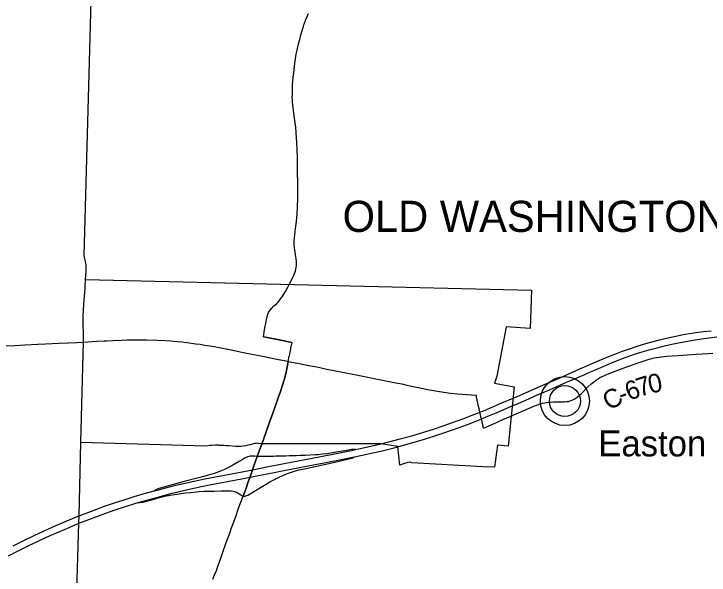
# Model space of a CAD drawing. Extents: x -29.6 to 34, y 0 to 22.
# Drawn here: x -18.092 to -16.109, y 3.352 to 4.953 of the extents above; entities that cross this region are included whole.
import ezdxf

# ---------------------------------------------------------------- set-up
doc = ezdxf.new("R2010")
doc.units = 0
for name, color, linetype in [('GM_X_City_Street', 7, 'Continuous'), ('GM_X_Corporation', 7, 'Continuous'), ('GM_X_Corporation_Text', 7, 'Continuous'), ('GM_X_County_Road', 7, 'Continuous'), ('GM_X_County_Road_Text', 7, 'Continuous'), ('GM_X_Interchange_Ramps', 7, 'Continuous'), ('GM_X_Interstate_Location', 7, 'Continuous'), ('GM_X_Interstate_Route', 7, 'Continuous'), ('GM_X_State_Route', 7, 'Continuous'), ('GM_X_Township', 7, 'Continuous'), ('GM_X_Unincorporated', 7, 'Continuous'), ('GM_X_Unincorporated_Location', 7, 'Continuous'), ('GM_X_Unincorporated_Text', 7, 'Continuous'), ('GM_X_US_Route', 7, 'Continuous')]:
    doc.layers.add(name, color=color, linetype=linetype)

msp = doc.modelspace()

# ---------------------------------------------------------------- linework, layer by layer
at = {"layer": 'GM_X_City_Street'}
msp.add_lwpolyline([(-17.3093, 3.9618), (-17.2826, 3.9563), (-17.2511, 3.9504), (-17.2283, 3.9458), (-17.1992, 3.9398), (-17.1547, 3.931), (-17.1159, 3.9231), (-17.0924, 3.9184), (-17.0644, 3.913), (-17.0267, 3.9054), (-17.0022, 3.9005), (-16.986, 3.8973), (-16.9713, 3.8944), (-16.9388, 3.8876), (-16.9069, 3.881), (-16.8839, 3.8768), (-16.8655, 3.8738), (-16.847, 3.8713), (-16.8273, 3.8691), (-16.8145, 3.868), (-16.7731, 3.8656)], dxfattribs=at)
at = {"layer": 'GM_X_Corporation'}
msp.add_lwpolyline([(-17.5447, 3.7201), (-17.9004, 3.7303), (-17.8934, 4.0173), (-17.8936, 4.0526), (-17.8938, 4.0563), (-17.8942, 4.0621), (-17.8943, 4.0708), (-17.8941, 4.0818), (-17.8939, 4.0923), (-17.8933, 4.1074), (-17.8923, 4.1254), (-17.8899, 4.1579), (-17.8888, 4.1712), (-17.8882, 4.1794), (-17.8876, 4.191), (-17.8874, 4.1953), (-16.6156, 4.1647), (-16.6198, 4.0556), (-16.6876, 4.0605), (-16.7147, 3.9197), (-16.7214, 3.9001), (-16.6648, 3.8891), (-16.6824, 3.7198), (-16.7125, 3.7232), (-16.7212, 3.6604), (-16.755, 3.6608), (-16.9566, 3.6725), (-16.9618, 3.6742), (-16.9684, 3.6736), (-16.9805, 3.67), (-16.9909, 3.6661), (-16.9967, 3.7189), (-17.0451, 3.7269), (-17.3853, 3.7262), (-17.3946, 3.728), (-17.3974, 3.7282), (-17.4009, 3.728), (-17.4049, 3.7273), (-17.4116, 3.7257), (-17.4184, 3.7239), (-17.425, 3.7224), (-17.4314, 3.7211), (-17.439, 3.7201), (-17.4459, 3.7193), (-17.4529, 3.7191), (-17.4598, 3.7192), (-17.468, 3.7198), (-17.4784, 3.7209), (-17.486, 3.7214), (-17.4935, 3.7219), (-17.4964, 3.722), (-17.5022, 3.7223), (-17.5051, 3.7223), (-17.508, 3.7224), (-17.512, 3.7224), (-17.5143, 3.7225), (-17.518, 3.7225), (-17.5272, 3.7222), (-17.532, 3.7218)], close=True, dxfattribs=at)
at = {"layer": 'GM_X_County_Road'}
for points in [[(-17.3799, 4.032), (-17.3644, 4.0288), (-17.3451, 4.0249), (-17.3262, 4.0212), (-17.3137, 4.0186), (-17.2987, 4.0153)], [(-16.5433, 3.8466), (-16.5418, 3.8466), (-16.5307, 3.8467), (-16.5214, 3.8467), (-16.5157, 3.8471), (-16.5106, 3.8478), (-16.5061, 3.8489), (-16.5023, 3.8501), (-16.4981, 3.8519), (-16.4941, 3.8541), (-16.4892, 3.8572), (-16.4846, 3.8606), (-16.4793, 3.8651), (-16.4733, 3.8706), (-16.4548, 3.8891), (-16.4462, 3.897), (-16.4395, 3.9027), (-16.4325, 3.908), (-16.4262, 3.9122), (-16.4207, 3.9155), (-16.4145, 3.9188), (-16.4081, 3.9218), (-16.3994, 3.9254), (-16.3771, 3.9337), (-16.3618, 3.9394), (-16.3465, 3.9452), (-16.3329, 3.9503), (-16.317, 3.9559), (-16.3027, 3.9608), (-16.2922, 3.9642), (-16.2805, 3.9681), (-16.2727, 3.9703), (-16.2664, 3.9717), (-16.2583, 3.973), (-16.2455, 3.9747), (-16.2299, 3.9763), (-16.2147, 3.9774), (-16.1979, 3.9786), (-16.1718, 3.9808), (-16.1462, 3.9825), (-16.1119, 3.9847), (-16.0991, 3.9857)], [(-16.7526, 3.7715), (-16.7533, 3.7744), (-16.7547, 3.7818), (-16.7562, 3.7887), (-16.7577, 3.7949), (-16.7584, 3.7979), (-16.7589, 3.8), (-16.7621, 3.8136), (-16.7629, 3.8169), (-16.7643, 3.8227), (-16.7667, 3.8335), (-16.7689, 3.8431), (-16.771, 3.8516), (-16.7712, 3.8523), (-16.7717, 3.8547), (-16.7725, 3.86), (-16.7731, 3.8656)], [(-16.6665, 3.8091), (-16.6242, 3.8277), (-16.6091, 3.834), (-16.5988, 3.8379), (-16.591, 3.8405), (-16.5848, 3.8422), (-16.5791, 3.8435), (-16.5727, 3.8445), (-16.5628, 3.8456), (-16.5535, 3.8463), (-16.5433, 3.8466)], [(-16.7526, 3.7715), (-16.7152, 3.7875), (-16.6971, 3.7958), (-16.6762, 3.8049), (-16.6665, 3.8091)]]:
    msp.add_lwpolyline(points, dxfattribs=at)
at = {"layer": 'GM_X_Interchange_Ramps'}
for points in [[(-17.1167, 3.7101), (-17.1192, 3.7105), (-17.1233, 3.7107), (-17.126, 3.7106), (-17.1295, 3.7103), (-17.1421, 3.708), (-17.1782, 3.7016), (-17.1989, 3.6984), (-17.2116, 3.6967), (-17.2238, 3.6955), (-17.2336, 3.6948), (-17.261, 3.6936), (-17.2755, 3.693), (-17.2865, 3.6926), (-17.2935, 3.6924), (-17.2964, 3.6923), (-17.3057, 3.6921), (-17.3162, 3.6918), (-17.3261, 3.6916), (-17.3371, 3.6913), (-17.3441, 3.691), (-17.3528, 3.6908), (-17.3598, 3.6906), (-17.3714, 3.6904), (-17.3895, 3.6906), (-17.3976, 3.6907)], [(-17.3976, 3.6907), (-17.4059, 3.6912), (-17.4126, 3.6915), (-17.4153, 3.6914), (-17.4182, 3.6911), (-17.4209, 3.6907), (-17.4253, 3.6893), (-17.4297, 3.6876), (-17.4338, 3.6855), (-17.4394, 3.6823), (-17.4498, 3.676), (-17.4675, 3.6658), (-17.4798, 3.6592), (-17.4908, 3.6538), (-17.5009, 3.6493), (-17.5117, 3.645), (-17.5233, 3.6411), (-17.5372, 3.637), (-17.5615, 3.6306), (-17.6066, 3.6189), (-17.6403, 3.6099), (-17.6749, 3.6003), (-17.6782, 3.5993), (-17.6807, 3.5983), (-17.6835, 3.597), (-17.6873, 3.5951), (-17.6904, 3.5933), (-17.6918, 3.5926)], [(-17.7372, 3.5592), (-17.7322, 3.5596), (-17.7291, 3.5598), (-17.7251, 3.5602), (-17.7207, 3.561), (-17.7177, 3.5619), (-17.6981, 3.5674), (-17.6767, 3.5732), (-17.6609, 3.5771), (-17.6461, 3.5802), (-17.6335, 3.5825), (-17.6202, 3.5845), (-17.6034, 3.5866), (-17.5872, 3.5882), (-17.5634, 3.5903), (-17.5506, 3.5912), (-17.5396, 3.5916), (-17.5215, 3.592), (-17.5011, 3.5923), (-17.4808, 3.5925), (-17.4726, 3.5922), (-17.4668, 3.5916), (-17.4628, 3.5908), (-17.4584, 3.5895), (-17.4552, 3.588), (-17.4522, 3.5863), (-17.4448, 3.5813), (-17.4425, 3.5797), (-17.44, 3.5784), (-17.438, 3.5776)]]:
    msp.add_lwpolyline(points, dxfattribs=at)
at = {"layer": 'GM_X_Interstate_Route'}
for points in [[(-17.6918, 3.5926), (-17.6902, 3.593), (-17.6586, 3.6013), (-17.6298, 3.6084), (-17.6162, 3.6116), (-17.5775, 3.6198), (-17.5473, 3.6264), (-17.4605, 3.6428), (-17.4205, 3.651), (-17.411, 3.6529), (-17.3653, 3.6618), (-17.3206, 3.6707), (-17.261, 3.682), (-17.2169, 3.6905), (-17.1726, 3.6992), (-17.1293, 3.7077), (-17.1167, 3.7101), (-17.0449, 3.7264), (-16.9901, 3.7406), (-16.957, 3.7499), (-16.9167, 3.7618), (-16.8956, 3.7685), (-16.8675, 3.7781), (-16.8334, 3.7901), (-16.8061, 3.8002), (-16.7881, 3.8071), (-16.7745, 3.8123), (-16.7648, 3.8162), (-16.7629, 3.8169), (-16.7524, 3.8212), (-16.7432, 3.825), (-16.7073, 3.8403), (-16.6568, 3.862), (-16.5832, 3.8943), (-16.5303, 3.9172), (-16.478, 3.9401), (-16.423, 3.964), (-16.3956, 3.9756), (-16.3784, 3.9825), (-16.3593, 3.9898), (-16.3335, 3.999), (-16.3114, 4.0062), (-16.2897, 4.0129), (-16.269, 4.0188), (-16.2504, 4.0236), (-16.2306, 4.0284), (-16.209, 4.0331), (-16.1873, 4.0374), (-16.1667, 4.041), (-16.1466, 4.0441), (-16.1258, 4.0468), (-16.1032, 4.0494)], [(-16.6609, 3.8391), (-16.6237, 3.8554), (-16.6053, 3.8635), (-16.5946, 3.8681), (-16.5828, 3.8732), (-16.5647, 3.8811), (-16.5156, 3.9025), (-16.4642, 3.9248), (-16.4525, 3.9298), (-16.438, 3.9361), (-16.4182, 3.9446), (-16.3829, 3.9597), (-16.3661, 3.9665), (-16.3563, 3.9702), (-16.3355, 3.9778), (-16.3161, 3.9843), (-16.3067, 3.9873), (-16.2803, 3.9948), (-16.2578, 4.0009), (-16.2363, 4.0062), (-16.2153, 4.011), (-16.1965, 4.015), (-16.1707, 4.0199), (-16.1494, 4.0236), (-16.131, 4.0265), (-16.1102, 4.0293), (-16.0876, 4.0314)], [(-16.9965, 3.7184), (-16.9214, 3.7401), (-16.8798, 3.7532), (-16.8659, 3.7577), (-16.8467, 3.7643), (-16.8188, 3.7744), (-16.791, 3.7849), (-16.7694, 3.7935), (-16.7596, 3.7974), (-16.7584, 3.7979), (-16.7451, 3.8033), (-16.7166, 3.8152), (-16.6733, 3.8337), (-16.6609, 3.8391)], [(-17.1201, 3.69), (-17.0421, 3.7064), (-17.0112, 3.7143), (-16.9965, 3.7184)], [(-17.3444, 3.6462), (-17.3361, 3.6478), (-17.277, 3.6591), (-17.2178, 3.671), (-17.1683, 3.6802), (-17.1265, 3.6885), (-17.1201, 3.69)], [(-17.4529, 3.625), (-17.4464, 3.6262), (-17.4184, 3.6318), (-17.3992, 3.6357), (-17.3444, 3.6462)], [(-17.7372, 3.5592), (-17.6875, 3.5731), (-17.6402, 3.586), (-17.5868, 3.5985), (-17.557, 3.6047), (-17.5288, 3.6104), (-17.4874, 3.6186), (-17.4529, 3.625)], [(-18.0935, 3.4357), (-18.067, 3.4491), (-18.0324, 3.4659), (-18.0077, 3.4776), (-17.9828, 3.489), (-17.9491, 3.5035), (-17.9179, 3.5164), (-17.9056, 3.5212), (-17.8936, 3.526), (-17.8625, 3.5377), (-17.8329, 3.5484), (-17.8049, 3.5581), (-17.7772, 3.5672), (-17.7489, 3.576), (-17.716, 3.5858), (-17.6918, 3.5926)], [(-18.1067, 3.4068), (-18.0773, 3.4222), (-18.0512, 3.4353), (-18.0171, 3.4517), (-17.9885, 3.4649), (-17.9699, 3.4732), (-17.941, 3.4856), (-17.9082, 3.4992), (-17.9061, 3.5), (-17.8784, 3.511), (-17.8582, 3.5187), (-17.8292, 3.5291), (-17.8033, 3.5382), (-17.7762, 3.5471), (-17.7473, 3.5561), (-17.7372, 3.5592)]]:
    msp.add_lwpolyline(points, dxfattribs=at)
at = {"layer": 'GM_X_State_Route'}
msp.add_line((-17.3136, 3.9404), (-17.3093, 3.9618), dxfattribs=at)
for points in [[(-17.2649, 4.9214), (-17.2642, 4.9233), (-17.2589, 4.9369), (-17.2548, 4.9471), (-17.2517, 4.9541)], [(-17.3066, 4.1815), (-17.2946, 4.2048), (-17.2912, 4.2124), (-17.2889, 4.2192), (-17.2875, 4.225), (-17.2869, 4.2297), (-17.2862, 4.2357), (-17.2859, 4.2411), (-17.2861, 4.2471), (-17.287, 4.2554), (-17.2888, 4.2665), (-17.2906, 4.2786), (-17.2918, 4.2862), (-17.2924, 4.2926), (-17.2925, 4.2984), (-17.2923, 4.3049), (-17.2915, 4.3142), (-17.2894, 4.3326), (-17.2876, 4.3471), (-17.2861, 4.3604), (-17.2848, 4.3719), (-17.2841, 4.3806), (-17.283, 4.4033), (-17.2825, 4.4242), (-17.2823, 4.444), (-17.2823, 4.4586), (-17.2825, 4.476), (-17.2828, 4.4964), (-17.2829, 4.5069), (-17.283, 4.5244), (-17.2831, 4.5272), (-17.2832, 4.5436), (-17.2838, 4.5663), (-17.2845, 4.5855), (-17.2864, 4.6133), (-17.2879, 4.6296), (-17.2893, 4.6423), (-17.2912, 4.6555), (-17.2942, 4.6769), (-17.2965, 4.6936), (-17.2973, 4.7018), (-17.2977, 4.7076), (-17.2978, 4.7135), (-17.2977, 4.7263), (-17.2974, 4.7414), (-17.297, 4.7502), (-17.2961, 4.7618), (-17.2951, 4.7728), (-17.293, 4.7925), (-17.2905, 4.8122), (-17.2887, 4.8249), (-17.2866, 4.8376), (-17.2841, 4.8496), (-17.2799, 4.8677), (-17.2767, 4.8802), (-17.2733, 4.8931), (-17.2701, 4.9043), (-17.2661, 4.9178), (-17.2649, 4.9214)], [(-17.3799, 4.032), (-17.3779, 4.0451), (-17.3768, 4.0522), (-17.3749, 4.0625), (-17.3736, 4.0696), (-17.3724, 4.0761), (-17.3704, 4.0852), (-17.3687, 4.0926), (-17.3675, 4.0965), (-17.3657, 4.1009), (-17.3637, 4.1045), (-17.3614, 4.108), (-17.3576, 4.1125), (-17.3552, 4.115), (-17.3531, 4.1171), (-17.3501, 4.1199), (-17.3424, 4.1268), (-17.3392, 4.1301), (-17.3355, 4.1345), (-17.333, 4.1376), (-17.3312, 4.1399), (-17.3285, 4.1436), (-17.3264, 4.1463), (-17.3235, 4.1507), (-17.3217, 4.1536), (-17.3174, 4.1612), (-17.3106, 4.1734), (-17.307, 4.1807), (-17.3066, 4.1815)], [(-17.2987, 4.0153), (-17.3137, 4.0186), (-17.3262, 4.0212), (-17.3451, 4.0249), (-17.3644, 4.0288), (-17.3799, 4.032)], [(-17.3093, 3.9618), (-17.3064, 3.9765), (-17.3061, 3.9781), (-17.3031, 3.9925), (-17.3025, 3.9954), (-17.3017, 3.9993), (-17.2987, 4.0153)], [(-17.3851, 3.7257), (-17.3726, 3.7608), (-17.3628, 3.7888), (-17.3533, 3.8145), (-17.3439, 3.8408), (-17.3369, 3.8605), (-17.3324, 3.8731), (-17.3266, 3.8908), (-17.3203, 3.9119), (-17.3175, 3.9232), (-17.3167, 3.9264), (-17.3136, 3.9404)], [(-17.3976, 3.6907), (-17.3912, 3.7088), (-17.3851, 3.7257)], [(-17.4092, 3.6582), (-17.4074, 3.6635), (-17.3976, 3.6907)], [(-17.438, 3.5776), (-17.4298, 3.5998), (-17.4234, 3.6179), (-17.4214, 3.6234), (-17.4184, 3.6318), (-17.4171, 3.6354), (-17.4152, 3.6409), (-17.411, 3.6529), (-17.4092, 3.6582)], [(-17.5246, 3.3403), (-17.5194, 3.3527), (-17.5144, 3.3657), (-17.5084, 3.3821), (-17.5048, 3.392), (-17.5027, 3.3974), (-17.4968, 3.4145), (-17.486, 3.4453), (-17.4763, 3.4715), (-17.4709, 3.4875), (-17.4675, 3.4968), (-17.4599, 3.5169), (-17.4512, 3.5429), (-17.438, 3.5776)]]:
    msp.add_lwpolyline(points, dxfattribs=at)
at = {"layer": 'GM_X_Township'}
msp.add_lwpolyline([(-17.9131, 3.2755), (-17.9063, 3.5005), (-17.9055, 3.5219), (-17.9004, 3.7303), (-17.8934, 4.0173), (-17.8936, 4.0526), (-17.8938, 4.0563), (-17.8942, 4.0621), (-17.8943, 4.0708), (-17.8941, 4.0818), (-17.8939, 4.0923), (-17.8933, 4.1074), (-17.8923, 4.1254), (-17.8899, 4.1579), (-17.8888, 4.1712), (-17.8882, 4.1794), (-17.8876, 4.191), (-17.8874, 4.1953), (-17.8868, 4.2067), (-17.8865, 4.2096), (-17.886, 4.2159), (-17.8856, 4.2293), (-17.8857, 4.2363), (-17.8862, 4.2409), (-17.8873, 4.2466), (-17.8892, 4.2545), (-17.8904, 4.2596), (-17.8914, 4.263), (-17.8917, 4.2636), (-17.8676, 5.1286)], dxfattribs=at)
at = {"layer": 'GM_X_Unincorporated'}
for radius in [0.0698, 0.0442]:
    msp.add_circle((-16.5207, 3.8487), radius, dxfattribs=at)
at = {"layer": 'GM_X_Unincorporated_Location'}
msp.add_line((-16.5207, 3.8487), (-16.5207, 3.8487), dxfattribs=at)
at = {"layer": 'GM_X_US_Route'}
msp.add_line((-17.3093, 3.9618), (-17.3136, 3.9404), dxfattribs=at)
for points in [[(-16.6609, 3.8391), (-16.6237, 3.8554), (-16.6053, 3.8635), (-16.5946, 3.8681), (-16.5828, 3.8732), (-16.5647, 3.8811), (-16.5156, 3.9025), (-16.4642, 3.9248), (-16.4525, 3.9298), (-16.438, 3.9361), (-16.4182, 3.9446), (-16.3829, 3.9597), (-16.3661, 3.9665), (-16.3563, 3.9702), (-16.3355, 3.9778), (-16.3161, 3.9843), (-16.3067, 3.9873), (-16.2803, 3.9948), (-16.2578, 4.0009), (-16.2363, 4.0062), (-16.2153, 4.011), (-16.1965, 4.015), (-16.1707, 4.0199), (-16.1494, 4.0236), (-16.131, 4.0265), (-16.1102, 4.0293), (-16.0876, 4.0314)], [(-18.1192, 4.0059), (-18.0895, 4.0073), (-18.0605, 4.0088), (-18.0419, 4.0096), (-18.0242, 4.0106), (-18.0229, 4.0107), (-18.002, 4.0117), (-17.9625, 4.0137), (-17.9389, 4.0149)], [(-17.9389, 4.0149), (-17.937, 4.015), (-17.9129, 4.0158), (-17.8932, 4.0168), (-17.8811, 4.0174)], [(-17.8811, 4.0174), (-17.8681, 4.0182), (-17.8555, 4.019), (-17.834, 4.02), (-17.8267, 4.0204)], [(-17.8267, 4.0204), (-17.8084, 4.0212), (-17.7846, 4.0223), (-17.7683, 4.0229), (-17.7474, 4.0233), (-17.7264, 4.0235), (-17.7125, 4.0233), (-17.6834, 4.0224), (-17.6584, 4.0212), (-17.6438, 4.0202), (-17.6259, 4.0187), (-17.6126, 4.0174), (-17.5987, 4.0157), (-17.5733, 4.0123), (-17.5606, 4.0105), (-17.5477, 4.0085)], [(-17.5477, 4.0085), (-17.5262, 4.0051), (-17.5107, 4.0023), (-17.4725, 3.9947), (-17.4422, 3.9885), (-17.4131, 3.9828), (-17.3828, 3.9768), (-17.3423, 3.9685), (-17.3162, 3.9632), (-17.3093, 3.9618)], [(-17.3136, 3.9404), (-17.3167, 3.9264), (-17.3175, 3.9232), (-17.3203, 3.9119), (-17.3266, 3.8908), (-17.3324, 3.8731), (-17.3369, 3.8605), (-17.3439, 3.8408), (-17.3533, 3.8145), (-17.3628, 3.7888), (-17.3726, 3.7608), (-17.3851, 3.7257)], [(-16.9965, 3.7184), (-16.9214, 3.7401), (-16.8798, 3.7532), (-16.8659, 3.7577), (-16.8467, 3.7643), (-16.8188, 3.7744), (-16.791, 3.7849), (-16.7694, 3.7935), (-16.7596, 3.7974), (-16.7584, 3.7979), (-16.7451, 3.8033), (-16.7166, 3.8152), (-16.6733, 3.8337), (-16.6609, 3.8391)], [(-17.3851, 3.7257), (-17.3912, 3.7088), (-17.3976, 3.6907)], [(-17.1201, 3.69), (-17.0421, 3.7064), (-17.0112, 3.7143), (-16.9965, 3.7184)], [(-17.3976, 3.6907), (-17.4074, 3.6635), (-17.4092, 3.6582)], [(-17.3722, 3.6116), (-17.3619, 3.6178), (-17.3472, 3.6261), (-17.3358, 3.6319), (-17.3252, 3.6368), (-17.3144, 3.6412), (-17.3034, 3.6451), (-17.2917, 3.6487), (-17.2788, 3.6522), (-17.2629, 3.6558), (-17.1933, 3.6707), (-17.1644, 3.6769), (-17.1291, 3.6854), (-17.1255, 3.6865), (-17.1226, 3.6878), (-17.1214, 3.6886), (-17.1201, 3.69)], [(-17.4092, 3.6582), (-17.411, 3.6529), (-17.4152, 3.6409), (-17.4171, 3.6354), (-17.4184, 3.6318), (-17.4214, 3.6234), (-17.4234, 3.6179), (-17.4298, 3.5998), (-17.438, 3.5776)], [(-17.438, 3.5776), (-17.4353, 3.5774), (-17.4328, 3.5776), (-17.4304, 3.5781), (-17.4278, 3.5789), (-17.425, 3.5801), (-17.4104, 3.5889), (-17.3929, 3.5993), (-17.3722, 3.6116)]]:
    msp.add_lwpolyline(points, dxfattribs=at)

# ---------------------------------------------------------------- texts
at = {"layer": 'GM_X_Corporation_Text'}
msp.add_text('OLD WASHINGTON', height=0.088778, rotation=0, dxfattribs=at).set_placement((-17.1544, 4.3311))
at = {"layer": 'GM_X_County_Road_Text'}
for s, rotation, p in [('0', 11.9457, (-16.2777, 3.8697)), ('6', 20.201, (-16.3378, 3.849)), ('7', 17.5117, (-16.3077, 3.8602)), ('C', 30.6458, (-16.3937, 3.8202)), ('-', 20.3879, (-16.3583, 3.8414))]:
    msp.add_text(s, height=0.0533, rotation=rotation, dxfattribs=at).set_placement(p)
at = {"layer": 'GM_X_Interstate_Location'}
for s in ['-', '.', ',']:
    msp.add_text(s, height=0.000178, dxfattribs=at).set_placement((-17.2237, 3.6702))
at = {"layer": 'GM_X_Unincorporated_Text'}
msp.add_text('Easton', height=0.07404, rotation=0, dxfattribs=at).set_placement((-16.4256, 3.6909))

doc.saveas('drawing.dxf')
